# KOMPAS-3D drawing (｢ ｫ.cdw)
File: created 14.09.2016 18:11:26, last saved 24.12.2016 15:27:20.
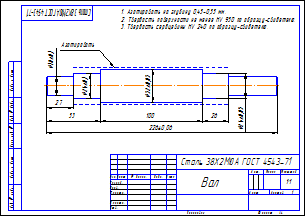
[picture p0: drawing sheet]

Sheet 1: A4, landscape

Title block, sheet 1: name: Вал; designation: Сталь 38Х2МЮА ГОСТ 4543-71; scale: 1:1; sheets: 1; sheet format: A4; stored path: C:\Users\nikit\OneDrive\Документы\Лабораторные\4 курс\вал.cdw

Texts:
  Никита
  Лит-Масса-Масштаб
  Материал-Предприятие
  1. Азотировать на глубину 0,45-0,55 мм.
  2. Твердость поверхности не менее HV 950 по образцу-свидетелю.
  3. Твердость сердцевины HV 240 по образцу-свидетелю.
  Азотировать
  Масштаб
  Изм.
  Лист
  № докум.
  Подп.
  Дата
  Лит.
  Разраб.
  Пров.
  Т.контр.
  Листов
  Н.контр.
  Утв.
  Инв. № подл.
  Подп. и дата
  Взам. инв. №
  Инв. № дубл.
  Стили документа
Dimensions and other numbers on the sheet: 226±0,06; 27; 53; 100; 18±0,1; 24±0,1; 32±0,03; 26; 1:1; 1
